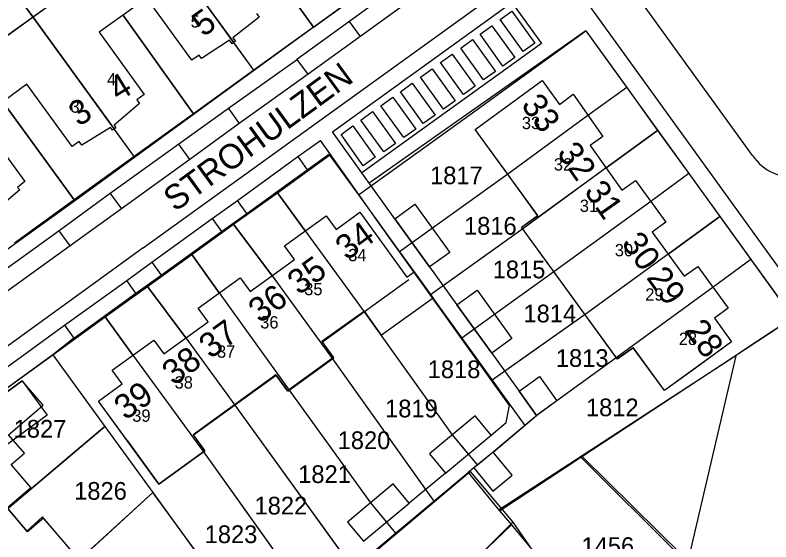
# Model space of a CAD drawing. Extents: x 148816 to 151297, y 399515 to 402500.
# Drawn here: x 149623.5 to 149700.3, y 400293.2 to 400346.7 of the extents above; entities that cross this region are included whole.
import ezdxf

# ---------------------------------------------------------------- set-up
doc = ezdxf.new("R2010")
doc.units = 0
for name, color, linetype in [('B01 Hoofdgebouw  [D] Norm', 7, 'Continuous'), ('B01 Hoofdgebouw  [T] Norm', 7, 'Continuous'), ('B01 hoofgebouw', 7, 'Continuous'), ('B02 Bijgebouw  [D] Norm', 7, 'Continuous'), ('B07 Tussenmuur  [D] Norm', 7, 'Continuous'), ('G01 perceelsgrens', 7, 'Continuous'), ('T04 Haag heg  [D] Gem', 7, 'Continuous'), ('V00 Kant verharding algemeen  [T] Norm', 7, 'Continuous'), ('Z01 perceelnummer', 7, 'Continuous'), ('Z02 huisnummer', 7, 'Continuous'), ('Z02 Huisnummer  [Tekst] Norm', 7, 'Continuous'), ('Z06 straatnaam', 7, 'Continuous')]:
    doc.layers.add(name, color=color, linetype=linetype)

msp = doc.modelspace()

# ---------------------------------------------------------------- linework, layer by layer
at = {"layer": 'B01 Hoofdgebouw  [D] Norm'}
for points in [[(149622.706, 400296.619), (149625.123, 400298.684), (149623.122, 400301.026), (149624.46, 400302.169), (149622.856, 400304.047), (149626.369, 400307.048), (149624.251, 400309.527)], [(149672.98, 400296.5), (149674.089, 400295.177)], [(149674.089, 400295.177), (149657.722, 400278.875), (149659.841, 400276.523), (149653.732, 400270.84), (149653.858, 400270.636), (149650.817, 400267.909), (149650.085, 400268.702), (149648.27, 400266.882), (149650.545, 400264.355)]]:
    msp.add_lwpolyline(points, dxfattribs=at)
at = {"layer": 'B01 Hoofdgebouw  [T] Norm'}
for p, q in [((149641.17, 400276.31), (149669.77, 400300.33)), ((149669.77, 400300.33), (149672.98, 400296.5))]:
    msp.add_line(p, q, dxfattribs=at)
for points in [[(149622.162, 400344.236), (149628.494, 400348.808), (149627.615, 400350.025), (149633.445, 400354.233), (149634.323, 400353.017), (149640.663, 400357.595), (149639.785, 400358.811), (149645.59, 400363.003), (149646.468, 400361.787), (149652.824, 400366.377), (149651.946, 400367.593), (149657.775, 400371.802), (149658.653, 400370.586), (149664.985, 400375.158), (149664.107, 400376.374), (149669.936, 400380.583)], [(149648.065, 400346.845), (149648.328, 400346.48), (149645.658, 400344.386), (149645.92, 400344.032), (149645.581, 400343.781), (149645.319, 400344.135), (149642.472, 400342.281), (149642.219, 400342.634), (149641.489, 400342.108), (149636.906, 400348.457), (149632.062, 400344.96), (149636.645, 400338.611), (149635.892, 400338.073), (149636.149, 400337.719), (149633.574, 400335.505), (149633.755, 400335.254), (149633.407, 400335.008), (149633.227, 400335.256), (149630.307, 400333.471), (149630.046, 400333.838), (149629.332, 400333.33), (149624.708, 400339.661), (149619.874, 400336.13), (149624.498, 400329.799), (149623.773, 400329.19), (149623.993, 400328.931)], [(149677.074, 400340.034), (149678.833, 400337.623), (149680.226, 400338.646)], [(149685.175, 400328.889), (149686.576, 400329.876), (149689.64, 400325.651)], [(149623.993, 400328.931), (149621.403, 400326.73), (149621.597, 400326.463), (149621.258, 400326.216), (149621.062, 400326.477), (149618.164, 400324.716), (149617.91, 400325.088), (149617.174, 400324.55)], [(149662.094, 400325.992), (149665.632, 400321.099)], [(149691.511, 400320.15), (149692.904, 400321.152), (149695.977, 400316.924)], [(149668.414, 400317.249), (149671.949, 400312.35)], [(149624.251, 400309.527), (149613.395, 400301.621)], [(149674.74, 400308.476), (149676.515, 400306.004)], [(149667.246, 400300.159), (149671.887, 400304.025)], [(149630.157, 400291.202), (149626.424, 400295.591), (149624.789, 400294.182), (149622.706, 400296.619)]]:
    msp.add_lwpolyline(points, dxfattribs=at)
for points in [[(149674.973, 400325.13), (149676.638, 400326.346), (149670.272, 400335.071), (149677.074, 400340.034), (149678.833, 400337.623), (149680.226, 400338.646), (149683.242, 400334.365), (149681.956, 400333.459), (149685.175, 400328.889), (149686.576, 400329.876), (149689.64, 400325.651), (149688.252, 400324.644), (149691.511, 400320.15), (149692.904, 400321.152), (149695.977, 400316.924), (149694.578, 400315.907), (149696.33, 400313.497), (149689.503, 400308.534), (149686.34, 400312.886), (149684.692, 400311.76)], [(149665.632, 400321.099), (149662.094, 400325.992), (149664.152, 400327.48), (149667.69, 400322.587)], [(149659.025, 400316.617), (149654.704, 400313.534), (149655.879, 400311.915), (149651.201, 400308.52), (149650.026, 400310.139), (149641.625, 400304.042), (149642.8, 400302.423), (149638.122, 400299.028), (149631.99, 400307.476), (149634.409, 400309.217), (149633.378, 400310.605), (149637.622, 400313.667), (149638.621, 400312.274), (149643.141, 400315.543), (149642.14, 400316.928), (149646.392, 400320.003), (149647.394, 400318.598), (149651.897, 400321.844), (149650.889, 400323.242), (149655.122, 400326.294), (149656.139, 400324.904), (149658.557, 400326.66), (149663.33, 400320.079), (149664.067, 400320.613), (149666.01, 400317.933), (149660.76, 400314.186)], [(149671.949, 400312.35), (149668.414, 400317.249), (149670.474, 400318.735), (149674.008, 400313.835)], [(149676.515, 400306.004), (149674.74, 400308.476), (149676.803, 400309.957), (149678.578, 400307.485)], [(149671.887, 400304.025), (149670.261, 400305.977), (149665.62, 400302.111), (149667.246, 400300.159)], [(149674.036, 400299.95), (149672.101, 400302.294), (149670.142, 400300.677), (149672.077, 400298.333)], [(149661.948, 400299.052), (149657.306, 400295.188), (149658.931, 400293.236), (149663.573, 400297.1)]]:
    msp.add_lwpolyline(points, close=True, dxfattribs=at)
at = {"layer": 'B01 hoofgebouw'}
for points in [[(149606.067, 400334.463), (149609.145, 400336.685), (149610.024, 400335.466), (149616.367, 400340.045), (149615.487, 400341.263), (149621.286, 400345.448), (149622.165, 400344.23), (149628.507, 400348.808), (149627.628, 400350.026), (149633.426, 400354.211), (149634.306, 400352.993), (149640.656, 400357.577), (149639.777, 400358.795), (149645.591, 400362.992), (149646.471, 400361.774), (149652.837, 400366.37), (149651.958, 400367.588), (149657.756, 400371.773), (149658.636, 400370.555), (149664.978, 400375.133), (149664.099, 400376.351), (149669.897, 400380.537)], [(149648.065, 400346.845), (149648.328, 400346.48), (149645.658, 400344.386), (149645.92, 400344.032), (149645.581, 400343.781), (149645.319, 400344.135), (149642.472, 400342.281), (149642.219, 400342.634), (149641.489, 400342.108), (149636.906, 400348.457), (149632.062, 400344.96), (149636.645, 400338.611), (149635.892, 400338.073), (149636.149, 400337.719), (149633.574, 400335.505)], [(149633.574, 400335.505), (149633.755, 400335.254), (149633.407, 400335.008), (149633.227, 400335.256), (149630.307, 400333.471), (149630.046, 400333.838), (149629.332, 400333.33), (149624.708, 400339.661), (149619.874, 400336.13), (149624.498, 400329.799), (149623.773, 400329.19), (149623.993, 400328.931), (149621.403, 400326.73), (149621.597, 400326.463), (149621.258, 400326.216), (149621.062, 400326.477), (149618.164, 400324.716), (149617.91, 400325.088), (149617.174, 400324.55), (149612.605, 400330.893), (149610.025, 400329.009), (149607.076, 400333.047)], [(149673.219, 400331.032), (149670.272, 400335.071), (149677.074, 400340.034), (149678.833, 400337.623), (149680.226, 400338.646), (149683.242, 400334.365), (149681.956, 400333.459), (149685.175, 400328.889), (149686.576, 400329.876), (149689.64, 400325.651), (149688.252, 400324.644), (149691.511, 400320.15), (149692.904, 400321.152), (149695.977, 400316.924), (149694.578, 400315.907), (149696.33, 400313.497), (149692.286, 400310.557)], [(149689.503, 400308.534), (149686.345, 400312.892), (149684.725, 400311.718), (149674.992, 400325.148), (149676.612, 400326.323), (149673.219, 400331.032)], [(149662.094, 400325.992), (149664.152, 400327.48)], [(149664.152, 400327.48), (149667.69, 400322.587)], [(149634.927, 400303.43), (149631.99, 400307.476), (149634.409, 400309.217), (149633.378, 400310.605), (149637.622, 400313.667), (149638.621, 400312.274), (149643.141, 400315.543), (149642.14, 400316.928), (149646.392, 400320.003), (149647.394, 400318.598), (149651.897, 400321.844), (149650.889, 400323.242), (149655.122, 400326.294), (149656.139, 400324.904), (149658.557, 400326.66), (149663.33, 400320.079)], [(149665.632, 400321.099), (149662.094, 400325.992)], [(149667.69, 400322.587), (149665.632, 400321.099)], [(149663.33, 400320.079), (149664.067, 400320.613), (149666.01, 400317.933)], [(149638.123, 400299.027), (149642.813, 400302.411), (149641.642, 400304.034), (149650.064, 400310.111), (149651.235, 400308.489), (149655.925, 400311.873), (149654.754, 400313.496), (149663.517, 400319.819)], [(149668.414, 400317.249), (149670.474, 400318.735)], [(149670.474, 400318.735), (149674.008, 400313.835)], [(149671.949, 400312.35), (149668.414, 400317.249)], [(149674.008, 400313.835), (149671.949, 400312.35)], [(149692.286, 400310.557), (149689.503, 400308.534)], [(149616.026, 400298.542), (149613.395, 400301.621), (149624.251, 400309.527), (149626.794, 400306.035)], [(149676.525, 400306.005), (149674.736, 400308.479), (149676.796, 400309.969), (149678.585, 400307.495)], [(149674.74, 400308.476), (149676.803, 400309.957)], [(149676.803, 400309.957), (149678.578, 400307.485)], [(149676.515, 400306.004), (149674.74, 400308.476)], [(149678.578, 400307.485), (149676.515, 400306.004)], [(149678.585, 400307.495), (149676.525, 400306.005)], [(149626.794, 400306.035), (149619.314, 400300.587)], [(149670.261, 400305.977), (149665.62, 400302.111)], [(149671.887, 400304.025), (149670.261, 400305.977)], [(149634.927, 400303.43), (149638.123, 400299.027)], [(149667.246, 400300.159), (149671.887, 400304.025)], [(149665.62, 400302.111), (149667.246, 400300.159)], [(149672.101, 400302.294), (149670.142, 400300.677)], [(149674.036, 400299.95), (149672.101, 400302.294)], [(149619.314, 400300.587), (149624.72, 400294.264)], [(149645.5, 400275.95), (149643.24, 400273.96), (149641.17, 400276.31), (149669.77, 400300.33), (149672.98, 400296.5)], [(149670.142, 400300.677), (149672.077, 400298.333)], [(149672.077, 400298.333), (149674.036, 400299.95)], [(149661.948, 400299.052), (149657.306, 400295.188)], [(149663.573, 400297.1), (149661.948, 400299.052)], [(149672.98, 400296.5), (149674.089, 400295.177), (149657.722, 400278.875), (149659.841, 400276.523), (149653.732, 400270.84), (149653.858, 400270.636), (149650.817, 400267.909), (149650.085, 400268.702), (149648.27, 400266.882), (149650.545, 400264.355), (149648.45, 400262.37)], [(149658.931, 400293.236), (149663.573, 400297.1)], [(149630.043, 400291.348), (149626.291, 400295.717), (149624.72, 400294.264)], [(149657.306, 400295.188), (149658.931, 400293.236)]]:
    msp.add_lwpolyline(points, dxfattribs=at)
at = {"layer": 'B02 Bijgebouw  [D] Norm'}
for p, q in [((149667.941, 400304.044), (149669.566, 400302.092)), ((149659.627, 400297.12), (149661.251, 400295.168))]:
    msp.add_line(p, q, dxfattribs=at)
at = {"layer": 'B07 Tussenmuur  [D] Norm'}
for p, q in [((149637.476, 400355.282), (149645.75, 400343.906)), ((149637.476, 400355.282), (149645.75, 400343.906)), ((149625.327, 400346.513), (149633.581, 400335.131)), ((149625.327, 400346.513), (149633.581, 400335.131)), ((149681.733, 400336.507), (149673.579, 400330.539)), ((149681.733, 400336.507), (149673.579, 400330.539)), ((149683.568, 400331.17), (149675.109, 400324.986)), ((149683.568, 400331.17), (149675.109, 400324.986)), ((149688.108, 400327.764), (149678.278, 400320.614)), ((149688.108, 400327.764), (149678.278, 400320.614)), ((149653.005, 400324.768), (149658.979, 400316.545)), ((149653.005, 400324.768), (149658.979, 400316.545)), ((149689.885, 400322.392), (149681.435, 400316.257)), ((149689.885, 400322.392), (149681.435, 400316.257)), ((149649.634, 400320.213), (149655.771, 400311.762)), ((149649.634, 400320.213), (149655.771, 400311.762)), ((149694.442, 400319.035), (149684.604, 400311.885)), ((149694.442, 400319.035), (149684.604, 400311.885)), ((149644.269, 400318.468), (149651.381, 400308.594)), ((149644.269, 400318.468), (149651.381, 400308.594)), ((149640.88, 400313.908), (149645.851, 400307.071)), ((149640.88, 400313.908), (149645.851, 400307.071)), ((149635.497, 400312.134), (149639.082, 400307.22)), ((149635.497, 400312.134), (149639.082, 400307.22)), ((149639.082, 400307.22), (149642.657, 400302.319)), ((149639.082, 400307.22), (149642.657, 400302.319))]:
    msp.add_line(p, q, dxfattribs=at)
at = {"layer": 'G01 perceelsgrens'}
for points in [[(149653.857, 400345.484), (149646.652, 400355.477), (149642.68, 400360.89), (149635.842, 400370.046)], [(149647.791, 400341.102), (149637.476, 400355.282), (149630.031, 400365.85)], [(149635.625, 400332.32), (149625.327, 400346.513), (149617.664, 400356.919)], [(149629.512, 400327.909), (149622.285, 400337.891), (149618.382, 400343.352), (149611.62, 400352.555)], [(149653.857, 400345.484), (149659.935, 400349.87)], [(149641.658, 400336.673), (149634.482, 400346.707)], [(149653.857, 400345.484), (149647.791, 400341.102)], [(149669.374, 400336.334), (149681.5, 400345.09)], [(149681.5, 400345.09), (149685.667, 400339.326)], [(149647.791, 400341.102), (149641.658, 400336.673)], [(149685.667, 400339.326), (149681.733, 400336.507), (149673.579, 400330.539)], [(149685.667, 400339.326), (149688.81, 400334.974)], [(149641.658, 400336.673), (149635.625, 400332.32)], [(149658.403, 400328.433), (149669.374, 400336.334)], [(149688.81, 400334.974), (149683.568, 400331.17)], [(149688.81, 400334.974), (149691.978, 400330.592)], [(149635.625, 400332.32), (149629.512, 400327.909)], [(149650.179, 400328.649), (149655.483, 400332.474)], [(149655.483, 400332.474), (149658.403, 400328.433)], [(149683.568, 400331.17), (149676.744, 400326.182)], [(149673.579, 400330.539), (149665.922, 400325.033), (149662.597, 400322.628)], [(149691.978, 400330.592), (149688.108, 400327.764), (149678.278, 400320.614)], [(149691.978, 400330.592), (149695.126, 400326.23)], [(149645.725, 400325.435), (149650.179, 400328.649)], [(149650.179, 400328.649), (149653.005, 400324.768), (149658.979, 400316.545)], [(149629.512, 400327.909), (149623.452, 400323.534)], [(149658.403, 400328.433), (149662.597, 400322.628)], [(149676.744, 400326.182), (149675.109, 400324.986)], [(149695.126, 400326.23), (149689.885, 400322.392), (149681.435, 400316.257)], [(149695.126, 400326.23), (149698.28, 400321.862)], [(149641.48, 400322.366), (149645.725, 400325.435)], [(149645.725, 400325.435), (149649.634, 400320.213), (149655.771, 400311.762)], [(149675.109, 400324.986), (149665.734, 400318.281)], [(149662.597, 400322.628), (149664.239, 400320.355)], [(149636.967, 400319.113), (149641.48, 400322.366)], [(149641.48, 400322.366), (149644.269, 400318.468), (149651.381, 400308.594)], [(149698.28, 400321.862), (149694.442, 400319.035)], [(149698.28, 400321.862), (149702.554, 400315.935)], [(149664.239, 400320.355), (149665.734, 400318.281)], [(149678.278, 400320.614), (149672.241, 400316.286), (149668.907, 400313.88)], [(149632.688, 400316.024), (149636.967, 400319.113)], [(149636.967, 400319.113), (149640.88, 400313.908), (149645.851, 400307.071)], [(149694.442, 400319.035), (149684.604, 400311.885)], [(149665.734, 400318.281), (149668.907, 400313.88)], [(149658.979, 400316.545), (149667.941, 400304.044), (149670.499, 400300.972)], [(149627.354, 400312.16), (149632.688, 400316.024)], [(149632.688, 400316.024), (149635.497, 400312.134), (149642.667, 400302.306)], [(149681.435, 400316.257), (149671.992, 400309.601)], [(149681.005, 400301.76), (149702.554, 400315.935)], [(149668.907, 400313.88), (149671.992, 400309.601)], [(149605.043, 400296.061), (149627.354, 400312.16)], [(149627.354, 400312.16), (149632.633, 400304.887)], [(149655.771, 400311.762), (149666.081, 400297.29)], [(149684.604, 400311.885), (149678.585, 400307.495)], [(149671.992, 400309.601), (149675.316, 400304.994)], [(149651.381, 400308.594), (149659.627, 400297.12), (149662.192, 400294.037)], [(149678.585, 400307.495), (149676.525, 400306.005)], [(149645.851, 400307.071), (149657.881, 400290.431)], [(149676.525, 400306.005), (149675.316, 400304.994)], [(149622.771, 400296.544), (149632.633, 400304.887)], [(149632.633, 400304.887), (149637.505, 400298.184)], [(149675.316, 400304.994), (149672.101, 400302.294)], [(149642.667, 400302.306), (149651.878, 400289.407), (149653.762, 400286.985)], [(149672.101, 400302.294), (149670.499, 400300.972)], [(149672.755, 400296.333), (149681.005, 400301.76)], [(149681.005, 400301.76), (149691.001, 400291.831), (149684.254, 400284.843)], [(149670.142, 400300.677), (149669.567, 400300.206)], [(149670.499, 400300.972), (149670.142, 400300.677)], [(149666.081, 400297.29), (149669.567, 400300.206)], [(149669.567, 400300.206), (149672.755, 400296.333)], [(149618.033, 400280.335), (149625.697, 400287.214), (149630.043, 400291.348), (149637.505, 400298.184)], [(149637.505, 400298.184), (149637.69, 400297.929)], [(149637.69, 400297.929), (149642.726, 400290.998)], [(149662.192, 400294.037), (149666.081, 400297.29)], [(149672.755, 400296.333), (149673.958, 400294.886)], [(149673.958, 400294.886), (149664.946, 400286.261), (149655.05, 400276.907), (149636.48, 400259.524)], [(149673.958, 400294.886), (149677.859, 400290.193)], [(149657.881, 400290.431), (149662.192, 400294.037)]]:
    msp.add_lwpolyline(points, dxfattribs=at)
at = {"layer": 'T04 Haag heg  [D] Gem'}
for p, q in [((149617.664, 400356.919), (149625.327, 400346.513)), ((149646.652, 400355.477), (149653.857, 400345.484)), ((149634.482, 400346.707), (149641.658, 400336.673)), ((149647.791, 400341.102), (149645.75, 400343.906)), ((149685.667, 400339.326), (149681.733, 400336.507)), ((149622.285, 400337.891), (149629.512, 400327.909)), ((149635.625, 400332.32), (149633.581, 400335.131)), ((149683.568, 400331.17), (149688.81, 400334.974)), ((149673.579, 400330.539), (149665.922, 400325.033)), ((149691.978, 400330.592), (149688.108, 400327.764)), ((149653.006, 400324.768), (149650.179, 400328.649)), ((149689.885, 400322.392), (149695.126, 400326.23)), ((149649.634, 400320.213), (149645.725, 400325.435)), ((149675.109, 400324.986), (149667.009, 400319.193)), ((149644.269, 400318.468), (149641.48, 400322.366)), ((149698.28, 400321.862), (149694.442, 400319.035)), ((149678.278, 400320.614), (149672.241, 400316.286)), ((149640.88, 400313.908), (149636.967, 400319.113)), ((149658.979, 400316.545), (149667.941, 400304.044)), ((149635.497, 400312.134), (149632.688, 400316.024)), ((149681.435, 400316.257), (149673.277, 400310.507)), ((149702.554, 400315.935), (149697.167, 400312.392)), ((149629.506, 400313.859), (149627.354, 400312.16)), ((149627.354, 400312.16), (149604.043, 400295.34)), ((149627.354, 400312.16), (149632.633, 400304.887)), ((149655.771, 400311.762), (149665.232, 400298.482)), ((149696.768, 400312.057), (149672.708, 400296.414)), ((149684.604, 400311.885), (149678.585, 400307.495)), ((149696.768, 400312.056), (149691.873, 400291.249)), ((149651.381, 400308.594), (149659.627, 400297.12)), ((149645.851, 400307.071), (149657.881, 400290.431)), ((149632.633, 400304.887), (149622.771, 400296.544)), ((149632.633, 400304.887), (149637.505, 400298.184)), ((149642.667, 400302.306), (149651.878, 400289.407)), ((149681.163, 400301.796), (149691.326, 400291.787)), ((149637.505, 400298.184), (149630.043, 400291.348)), ((149637.505, 400298.184), (149642.726, 400290.998))]:
    msp.add_line(p, q, dxfattribs=at)
msp.add_lwpolyline([(149674.089, 400295.177), (149677.655, 400290.014)], dxfattribs=at)
at = {"layer": 'V00 Kant verharding algemeen  [T] Norm'}
for p, q in [((149653.641, 400335.386), (149673.951, 400350.038)), ((149651.475, 400343.732), (149629.917, 400328.06)), ((149645.193, 400337.211), (149640.16, 400333.577)), ((149636.54, 400323.055), (149653.641, 400335.386)), ((149652.254, 400332.316), (149654.556, 400333.964)), ((149660.706, 400325.261), (149655.516, 400332.623)), ((149647.079, 400326.539), (149653.206, 400330.971)), ((149633.195, 400328.553), (149628.004, 400324.785)), ((149643.552, 400326.026), (149646.123, 400327.871)), ((149637.402, 400321.573), (149643.552, 400326.026)), ((149638.353, 400320.262), (149644.505, 400324.706)), ((149636.54, 400323.055), (149603.486, 400299.129)), ((149665.632, 400321.099), (149668.414, 400317.249)), ((149635.803, 400318.435), (149638.353, 400320.262)), ((149628.549, 400315.183), (149634.865, 400319.735)), ((149671.949, 400312.35), (149674.74, 400308.476)), ((149672.101, 400302.294), (149676.515, 400306.004)), ((149667.246, 400300.159), (149663.573, 400297.1))]:
    msp.add_line(p, q, dxfattribs=at)
for points in [[(149686.048, 400368.727), (149651.475, 400343.732)], [(149653.288, 400340.686), (149652.152, 400342.212), (149685.414, 400366.283)], [(149686.923, 400365.015), (149653.296, 400340.679)], [(149698.457, 400332.43), (149684.789, 400351.343)], [(149680.945, 400348.959), (149703.987, 400317.066), (149706.488, 400315.911), (149715.253, 400344.17)], [(149672.805, 400346.236), (149673.994, 400347.103), (149676.331, 400343.855), (149675.133, 400343.002), (149672.805, 400346.236)], [(149657.457, 400346.042), (149658.573, 400344.505)], [(149670.765, 400344.751), (149671.954, 400345.618), (149674.291, 400342.37), (149673.093, 400341.517), (149670.765, 400344.751)], [(149681.513, 400345.103), (149669.912, 400336.945), (149659.508, 400329.629)], [(149681.513, 400345.103), (149702.461, 400316.117), (149703.917, 400317.163)], [(149668.806, 400343.337), (149669.995, 400344.204), (149672.332, 400340.956), (149671.134, 400340.103), (149668.806, 400343.337)], [(149666.751, 400341.864), (149667.94, 400342.731), (149670.277, 400339.483), (149669.079, 400338.63), (149666.751, 400341.864)], [(149652.202, 400342.193), (149645.193, 400337.211), (149646.304, 400335.669)], [(149664.714, 400340.375), (149665.903, 400341.242), (149668.24, 400337.994), (149667.042, 400337.141), (149664.714, 400340.375)], [(149653.296, 400340.679), (149646.304, 400335.669), (149641.272, 400332.017), (149634.324, 400327.01), (149629.114, 400323.249), (149622.159, 400318.228), (149604.762, 400305.571), (149600.748, 400302.651)], [(149662.667, 400338.905), (149663.856, 400339.772), (149666.193, 400336.524), (149664.995, 400335.671), (149662.667, 400338.905)], [(149660.701, 400337.483), (149661.89, 400338.35), (149664.227, 400335.102), (149663.029, 400334.249), (149660.701, 400337.483)], [(149658.661, 400336.029), (149659.85, 400336.896), (149662.187, 400333.648), (149660.989, 400332.795), (149658.661, 400336.029)], [(149657.843, 400335.426), (149660.108, 400332.263), (149658.894, 400331.385), (149656.641, 400334.557), (149657.843, 400335.426)], [(149641.272, 400332.017), (149640.16, 400333.577), (149633.195, 400328.553), (149634.324, 400327.01)], [(149643.552, 400326.026), (149644.505, 400324.706), (149647.079, 400326.539), (149646.123, 400327.871), (149652.254, 400332.316), (149653.206, 400330.971), (149655.516, 400332.623), (149654.556, 400333.964)], [(149662.094, 400325.992), (149658.758, 400330.683)], [(149629.917, 400328.06), (149597.017, 400304.375)], [(149671.887, 400304.025), (149673.424, 400305.305), (149673.757, 400307.014), (149660.706, 400325.261)], [(149629.114, 400323.249), (149628.004, 400324.785), (149621.006, 400319.756), (149622.159, 400318.228)], [(149604.642, 400297.788), (149628.549, 400315.183), (149629.506, 400313.859), (149635.803, 400318.435), (149634.865, 400319.735), (149637.402, 400321.573), (149638.353, 400320.262)]]:
    msp.add_lwpolyline(points, dxfattribs=at)
msp.add_lwpolyline([(149655.775, 400334.826), (149673.998, 400347.988), (149677, 400343.819), (149658.758, 400330.683)], close=True, dxfattribs=at)
for centre, radius, start, end in [((149702.576, 400335.151), 4.936, 213.44737, 342.23947), ((149876.381, 400511.181), 347.497, 218.38878, 224.71883)]:
    msp.add_arc(centre, radius, start, end, dxfattribs=at)

# ---------------------------------------------------------------- texts
at = {"layer": 'Z01 perceelnummer'}
for s, p in [('1817', (149665.684, 400329.509)), ('1816', (149669.133, 400324.38)), ('1815', (149672.052, 400319.947)), ('1814', (149675.178, 400315.47)), ('1813', (149678.47, 400310.947)), ('1818', (149665.446, 400309.804)), ('1819', (149661.118, 400305.819)), ('1812', (149681.524, 400305.933)), ('1827', (149623.377, 400303.761)), ('1820', (149656.298, 400302.595)), ('1821', (149652.286, 400299.147)), ('1826', (149629.523, 400297.449)), ('1822', (149647.851, 400295.954)), ('1823', (149642.781, 400293.044)), ('1456', (149681.074, 400291.84))]:
    msp.add_text(s, height=1.8, dxfattribs=at).set_placement(p)
at = {"layer": 'Z02 huisnummer'}
for s, rotation, p in [('5', 35.5177, (149642.643, 400344.41)), ('4', 31.46487, (149634.021, 400337.867)), ('33', 306.09057, (149674.87, 400337.539)), ('3', 31.46487, (149629.965, 400335.312)), ('32', 305.15154, (149678.519, 400332.692)), ('31', 305.15154, (149681.277, 400328.776)), ('34', 36.01053, (149657.245, 400321.691)), ('30', 305.93052, (149685.059, 400323.511)), ('35', 35.80411, (149652.364, 400318.174)), ('29', 305.93052, (149687.599, 400320.008)), ('36', 35.80411, (149648.395, 400315.314)), ('37', 35.88411, (149643.378, 400311.704)), ('28', 306.01053, (149691.47, 400314.654)), ('38', 35.88411, (149639.628, 400308.992)), ('39', 35.72413, (149634.747, 400305.457))]:
    msp.add_text(s, height=2.5, rotation=rotation, dxfattribs=at).set_placement(p)
at = {"layer": 'Z02 Huisnummer  [Tekst] Norm'}
for s, p in [('5', (149641.362, 400345.426)), ('4', (149632.867, 400339.554)), ('3', (149629.151, 400336.773)), ('33', (149675.015, 400335.107)), ('32', (149678.267, 400330.901)), ('31', (149680.9, 400326.695)), ('30', (149684.462, 400322.189)), ('34', (149657.373, 400321.687)), ('35', (149652.9, 400318.231)), ('29', (149687.559, 400317.683)), ('36', (149648.427, 400314.855)), ('28', (149690.966, 400313.177)), ('37', (149644.037, 400311.881)), ('38', (149639.73, 400308.747)), ('39', (149635.423, 400305.371))]:
    msp.add_text(s, height=1.25, dxfattribs=at).set_placement(p)
at = {"layer": 'Z06 straatnaam'}
msp.add_text('STROHULZEN', height=2.5, rotation=36.17064, dxfattribs=at).set_placement((149639.779, 400326.64))

doc.saveas('drawing.dxf')
